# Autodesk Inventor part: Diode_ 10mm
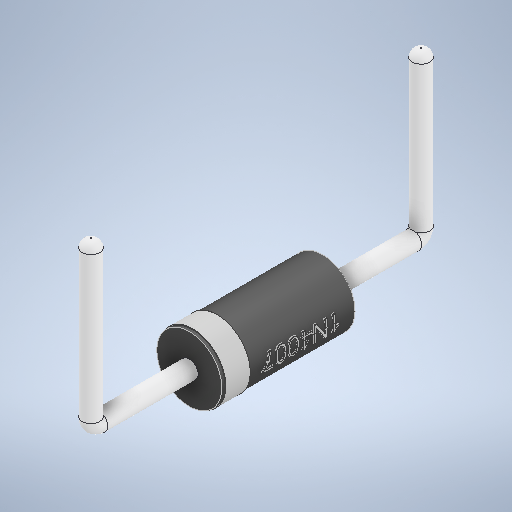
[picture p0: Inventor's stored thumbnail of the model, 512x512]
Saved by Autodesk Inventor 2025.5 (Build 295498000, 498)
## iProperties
Created: 2026-10
Part Number: Diode_ 10mm
Material: CFK
Document SubType Name: Modeling
Designer: Luis M
Density: 1.43 g/cm^3
Appearance: Valor por defecto
Author: Luis M
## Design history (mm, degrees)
feature "Body10"
feature "Body11"
feature "Body12"
feature "Body13"
feature "Body14"
feature "Body15"
feature "Body16"
feature "Body17"
feature "Body18"
feature "Body19"
node "Sólido1"
node "Sólido2"
node "Sólido3"
node "Sólido4"
node "Sólido5"
node "Sólido6"
node "Sólido7"
node "Sólido8"
node "Sólido9"
node "Sólido10"
